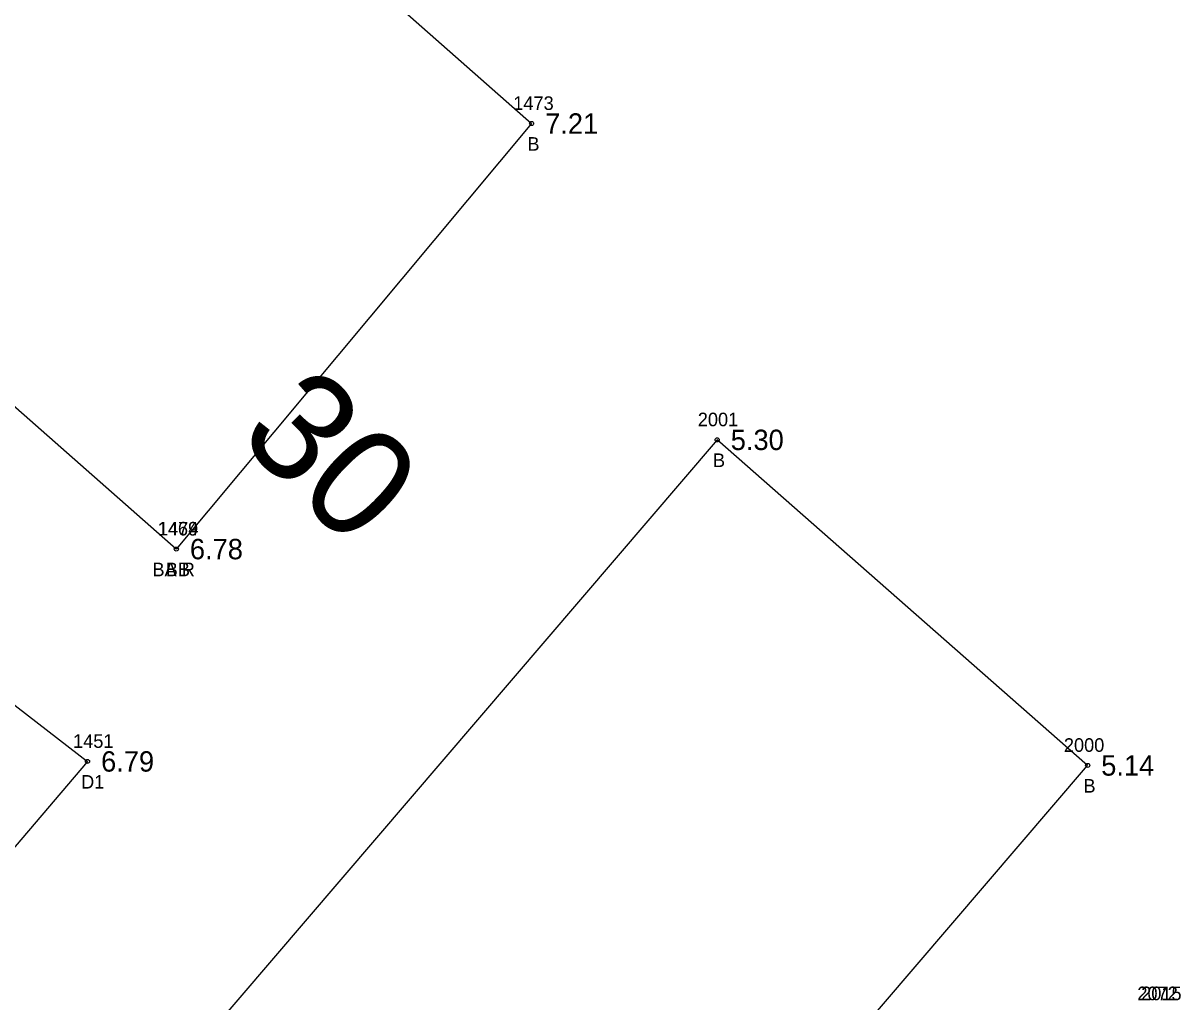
# Model space of a CAD drawing. Extents: x 2608598 to 2610682, y 641451 to 643526.
# Drawn here: x 2609219 to 2609304.2, y 643077.1 to 643149.1 of the extents above; entities that cross this region are included whole.
import ezdxf

# ---------------------------------------------------------------- set-up
doc = ezdxf.new("R2010")
doc.units = 0
for name, color, linetype in [('RD_EX_Bldg', 7, 'Continuous'), ('RD_EX_Bldg_txCode', 7, 'Continuous'), ('RD_EX_Driveway', 7, 'Continuous'), ('RD_EX_Driveway_txCode', 7, 'Continuous'), ('RD_EX_TX_Bldg_ELEV', 7, 'Continuous'), ('RD_EX_TX_Driveway_ELEV', 7, 'Continuous'), ('RD_HC_TX_Sta50', 7, 'Continuous'), ('RD_SMD_Locator', 7, 'Continuous')]:
    doc.layers.add(name, color=color, linetype=linetype)

msp = doc.modelspace()

# ---------------------------------------------------------------- linework, layer by layer
at = {"layer": 'RD_EX_Bldg'}
for points in [[(2609230.304, 643110.429), (2609161.523, 643171.054), (2609165.341, 643175.483), (2609187.674, 643202.373), (2609256.455, 643141.748), (2609230.304, 643110.429)], [(2609224.764, 643065.492), (2609252.034, 643041.529), (2609297.387, 643094.506), (2609270.116, 643118.468), (2609224.764, 643065.492)]]:
    msp.add_lwpolyline(points, dxfattribs=at)
at = {"layer": 'RD_EX_Driveway'}
msp.add_lwpolyline([(2609166.457, 643161.041), (2609160.17, 643148.257), (2609190.362, 643122.83), (2609213.317, 643102.873), (2609223.768, 643094.8), (2609208.755, 643077.174), (2609183.581, 643050.775)], dxfattribs=at)
at = {"layer": 'RD_SMD_Locator'}
for centre in [(2609256.455, 643141.748), (2609270.116, 643118.468), (2609230.304, 643110.429), (2609230.304, 643110.429), (2609223.768, 643094.8), (2609297.387, 643094.506)]:
    msp.add_circle(centre, 0.15, dxfattribs=at)

# ---------------------------------------------------------------- texts
at = {"layer": 'RD_EX_Bldg_txCode'}
for s, p in [('1473', (2609255.109, 643142.748)), ('B', (2609256.148, 643139.748)), ('2001', (2609268.691, 643119.468)), ('B', (2609269.809, 643116.468)), ('1469', (2609228.934, 643111.429)), ('1474', (2609228.957, 643111.429)), ('BA R', (2609228.548, 643108.429)), ('BB', (2609229.524, 643108.429)), ('2000', (2609295.639, 643095.506)), ('B', (2609297.08, 643092.506)), ('2072', (2609301.047, 643077.228)), ('2015', (2609301.33, 643077.228))]:
    msp.add_text(s, height=1, dxfattribs=at).set_placement(p)
at = {"layer": 'RD_EX_Driveway_txCode'}
for s, p in [('1451', (2609222.705, 643095.8)), ('D1', (2609223.296, 643092.8))]:
    msp.add_text(s, height=1, dxfattribs=at).set_placement(p)
at = {"layer": 'RD_EX_TX_Bldg_ELEV'}
for s, p in [('7.21', (2609257.455, 643140.998)), ('5.30', (2609271.116, 643117.718)), ('6.78', (2609231.304, 643109.679)), ('6.78', (2609231.304, 643109.679)), ('5.14', (2609298.387, 643093.756))]:
    msp.add_text(s, height=1.5, dxfattribs=at).set_placement(p)
at = {"layer": 'RD_EX_TX_Driveway_ELEV'}
msp.add_text('6.79', height=1.5, dxfattribs=at).set_placement((2609224.768, 643094.05))
at = {"layer": 'RD_HC_TX_Sta50'}
msp.add_text('30', height=8, rotation=316.01859, dxfattribs=at).set_placement((2609234.693, 643118.612))

doc.saveas('drawing.dxf')
